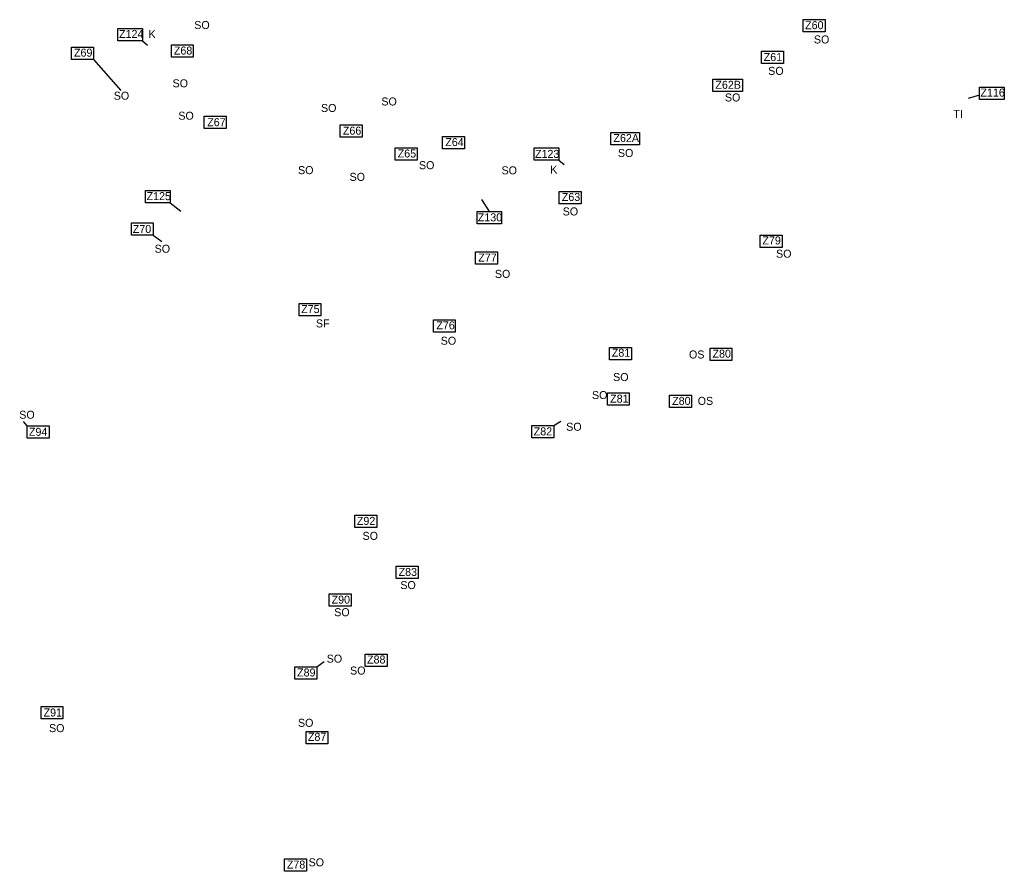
# Model space of a CAD drawing. Extents: x -443519 to -431242, y -1133468 to -1129615.
# Drawn here: x -441989 to -440759, y -1132600 to -1131536 of the extents above; entities that cross this region are included whole.
import ezdxf

# ---------------------------------------------------------------- set-up
doc = ezdxf.new("R2010")
doc.units = 0
for name, color, linetype in [('Vrstva 3', 7, 'Continuous'), ('Vrstva 4', 7, 'Continuous'), ('Vrstva 8', 7, 'Continuous')]:
    doc.layers.add(name, color=color, linetype=linetype)

msp = doc.modelspace()

# ---------------------------------------------------------------- linework, layer by layer
at = {"layer": 'Vrstva 3'}
for p, q in [((-441897, -1131586.3), (-441862.9, -1131625)), ((-440790.1, -1131630.6), (-440804.2, -1131634.7)), ((-441822.4, -1131805.7), (-441811.7, -1131813.5)), ((-441979.9, -1132043.8), (-441984.6, -1132038.4)), ((-441321.9, -1132043.4), (-441313.1, -1132037.9)), ((-441618.1, -1132344.9), (-441608.8, -1132338.2))]:
    msp.add_line(p, q, dxfattribs=at)
for points in [[(-441010.2, -1131536.4), (-440982.9, -1131536.4), (-440982.9, -1131551.8), (-441010.2, -1131551.8)], [(-441924.4, -1131570.9), (-441897, -1131570.9), (-441897, -1131586.3), (-441924.4, -1131586.3)], [(-441799.8, -1131567.7), (-441772.4, -1131567.7), (-441772.4, -1131583.1), (-441799.8, -1131583.1)], [(-441062.3, -1131575.9), (-441035, -1131575.9), (-441035, -1131591.3), (-441062.3, -1131591.3)], [(-441123.3, -1131610.9), (-441086, -1131610.9), (-441086, -1131626.3), (-441123.3, -1131626.3)], [(-440790.1, -1131620.9), (-440759.3, -1131620.9), (-440759.3, -1131636.2), (-440790.1, -1131636.2)], [(-441758.7, -1131656.9), (-441731.3, -1131656.9), (-441731.3, -1131672.3), (-441758.7, -1131672.3)], [(-441588.7, -1131668), (-441561.3, -1131668), (-441561.3, -1131683.4), (-441588.7, -1131683.4)], [(-441460.9, -1131682.5), (-441433.5, -1131682.5), (-441433.5, -1131697.9), (-441460.9, -1131697.9)], [(-441250.7, -1131677.5), (-441215, -1131677.5), (-441215, -1131692.9), (-441250.7, -1131692.9)], [(-441520.2, -1131696.6), (-441492.8, -1131696.6), (-441492.8, -1131712), (-441520.2, -1131712)], [(-441315.3, -1131751.1), (-441287.9, -1131751.1), (-441287.9, -1131766.5), (-441315.3, -1131766.5)], [(-441849.7, -1131790.3), (-441822.4, -1131790.3), (-441822.4, -1131805.7), (-441849.7, -1131805.7)], [(-441063.9, -1131805.5), (-441036.5, -1131805.5), (-441036.5, -1131820.9), (-441063.9, -1131820.9)], [(-441419.8, -1131826.6), (-441392.4, -1131826.6), (-441392.4, -1131842), (-441419.8, -1131842)], [(-441640.3, -1131891), (-441612.9, -1131891), (-441612.9, -1131906.4), (-441640.3, -1131906.4)], [(-441472.3, -1131911.6), (-441445, -1131911.6), (-441445, -1131927), (-441472.3, -1131927)], [(-441252.4, -1131945.8), (-441225, -1131945.8), (-441225, -1131961.2), (-441252.4, -1131961.2)], [(-441126.7, -1131946.9), (-441099.4, -1131946.9), (-441099.4, -1131962.3), (-441126.7, -1131962.3)], [(-441255, -1132002.7), (-441227.7, -1132002.7), (-441227.7, -1132018.1), (-441255, -1132018.1)], [(-441177.4, -1132005.6), (-441150, -1132005.6), (-441150, -1132021), (-441177.4, -1132021)], [(-441979.9, -1132043.8), (-441952.6, -1132043.8), (-441952.6, -1132059.2), (-441979.9, -1132059.2)], [(-441349.2, -1132043.4), (-441321.9, -1132043.4), (-441321.9, -1132058.8), (-441349.2, -1132058.8)], [(-441570.4, -1132155.6), (-441543.1, -1132155.6), (-441543.1, -1132171), (-441570.4, -1132171)], [(-441518.9, -1132219.3), (-441491.5, -1132219.3), (-441491.5, -1132234.7), (-441518.9, -1132234.7)], [(-441602.6, -1132253.6), (-441575.2, -1132253.6), (-441575.2, -1132269), (-441602.6, -1132269)], [(-441557.5, -1132329), (-441530.2, -1132329), (-441530.2, -1132344.4), (-441557.5, -1132344.4)], [(-441645.5, -1132344.9), (-441618.1, -1132344.9), (-441618.1, -1132360.3), (-441645.5, -1132360.3)], [(-441962.6, -1132394.5), (-441935.3, -1132394.5), (-441935.3, -1132409.9), (-441962.6, -1132409.9)], [(-441631.5, -1132425.8), (-441604.1, -1132425.8), (-441604.1, -1132441.2), (-441631.5, -1132441.2)], [(-441658.3, -1132585), (-441630.9, -1132585), (-441630.9, -1132600.4), (-441658.3, -1132600.4)]]:
    msp.add_lwpolyline(points, close=True, dxfattribs=at)
at = {"layer": 'Vrstva 8'}
for p, q in [((-441835.8, -1131562.7), (-441829.5, -1131568.4)), ((-441315.6, -1131712), (-441308.9, -1131717.3)), ((-441801.4, -1131765.3), (-441787.8, -1131775.7)), ((-441402.4, -1131775.9), (-441411.8, -1131761.2))]:
    msp.add_line(p, q, dxfattribs=at)
for points in [[(-441866.6, -1131547.3), (-441835.8, -1131547.3), (-441835.8, -1131562.7), (-441866.6, -1131562.7)], [(-441346.4, -1131696.6), (-441315.6, -1131696.6), (-441315.6, -1131712), (-441346.4, -1131712)], [(-441832.2, -1131749.9), (-441801.4, -1131749.9), (-441801.4, -1131765.3), (-441832.2, -1131765.3)], [(-441417.8, -1131775.9), (-441387.1, -1131775.9), (-441387.1, -1131791.3), (-441417.8, -1131791.3)]]:
    msp.add_lwpolyline(points, close=True, dxfattribs=at)

# ---------------------------------------------------------------- texts
at = {"layer": 'Vrstva 3'}
for s, p in [('Z60', (-441007.9, -1131548.3)), ('Z69', (-441921.5, -1131582.6)), ('Z68', (-441796.7, -1131580)), ('Z61', (-441059.6, -1131588.1)), ('Z62B', (-441120, -1131622.8)), ('Z116', (-440788.8, -1131632.5)), ('Z67', (-441755, -1131669.5)), ('Z66', (-441585.5, -1131680.1)), ('Z64', (-441457.5, -1131694.4)), ('Z62A', (-441247.4, -1131689.3)), ('Z65', (-441517, -1131708.6)), ('Z63', (-441311.9, -1131762.9)), ('Z70', (-441848, -1131802.9)), ('Z79', (-441061.2, -1131817.2)), ('Z77', (-441416.3, -1131838.6)), ('Z75', (-441637.6, -1131903)), ('Z76', (-441468.7, -1131923.3)), ('Z81', (-441249.4, -1131957.5)), ('Z80', (-441123.6, -1131958.7)), ('Z81', (-441251.5, -1132014.9)), ('Z80', (-441174, -1132017.7)), ('Z94', (-441977.8, -1132056.3)), ('Z82', (-441347, -1132055.8)), ('Z92', (-441568, -1132167.6)), ('Z83', (-441515.9, -1132231.4)), ('Z90', (-441599.6, -1132266)), ('Z88', (-441555.3, -1132340.8)), ('Z89', (-441642.7, -1132357)), ('Z91', (-441959.5, -1132407)), ('Z87', (-441629.2, -1132437.4)), ('Z78', (-441655.5, -1132597))]:
    msp.add_text(s, height=10, dxfattribs=at).set_placement(p)
at = {"layer": 'Vrstva 4'}
for s, p in [('SO', (-441771.2, -1131548.1)), ('K', (-441828.3, -1131559.4)), ('SO', (-440996.9, -1131566.1)), ('SO', (-441054, -1131605.4)), ('SO', (-441798.3, -1131620.9)), ('SO', (-441871.8, -1131636.4)), ('SO', (-441537.4, -1131643.6)), ('SO', (-441108.1, -1131638.6)), ('SO', (-441612.8, -1131651.7)), ('SO', (-441791.1, -1131661.4)), ('TI', (-440822.6, -1131659.1)), ('SO', (-441241.8, -1131708)), ('SO', (-441641.5, -1131729.4)), ('SO', (-441490.4, -1131723.2)), ('SO', (-441387.2, -1131729.7)), ('K', (-441326.3, -1131728.7)), ('SO', (-441577.1, -1131737.8)), ('SO', (-441310.8, -1131781)), ('SO', (-441820.7, -1131827.6)), ('SO', (-441044.2, -1131833.8)), ('SO', (-441395.5, -1131859)), ('SF', (-441619.2, -1131920.9)), ('SO', (-441463.2, -1131942.5)), ('OS', (-441153, -1131959.7)), ('SO', (-441247.8, -1131987.9)), ('SO', (-441274.2, -1132010.4)), ('OS', (-441142.1, -1132017.7)), ('SO', (-441989.9, -1132035)), ('SO', (-441306.4, -1132050)), ('SO', (-441560.9, -1132186.3)), ('SO', (-441513.7, -1132247.8)), ('SO', (-441596.3, -1132281.7)), ('SO', (-441605.7, -1132339.7)), ('SO', (-441576.5, -1132354.6)), ('SO', (-441641.6, -1132419.9)), ('SO', (-441952.7, -1132426.5)), ('SO', (-441628.3, -1132594.2))]:
    msp.add_text(s, height=10, dxfattribs=at).set_placement(p)
at = {"layer": 'Vrstva 8'}
for s, p in [('Z124', (-441865.2, -1131559.3)), ('Z123', (-441345.4, -1131709.1)), ('Z125', (-441830.8, -1131761.9)), ('Z130', (-441416.9, -1131788.4))]:
    msp.add_text(s, height=10, dxfattribs=at).set_placement(p)

doc.saveas('drawing.dxf')
